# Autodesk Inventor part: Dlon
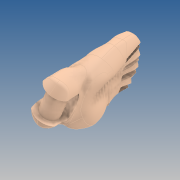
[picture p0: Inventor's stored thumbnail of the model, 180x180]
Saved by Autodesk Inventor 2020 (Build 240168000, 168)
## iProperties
Created: 2019-10
Part Number: Dlon
Material: GFRP
Document SubType Name: Modeling
Designer: yello
Density: 1.75 g/cm^3
Appearance: Default
Author: yello
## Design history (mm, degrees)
node "Palm"
workplane "Work Plane1"
workplane "Work Plane2"
sketch "Sketch13"
  geometry: L1 (0, 1.5)-(0, -1.5); A1 r 1.5 centre (0, 0) between (0, 1.5) and (0, -1.5)
  constraints: 2 end point, 2 point on circle, 1 centre point, 1 vertical
  dimensions: "d18" = 3 diameter of A1
sketch "Sketch14"
  geometry: L1 (0, -1.5)-(0, 1.5); A1 r 1.5 centre (0, 0) between (0, -1.5) and (0, 1.5); 1 further point
  constraints: 2 end point, 2 point on circle, 1 centre point, 1 vertical
  dimensions: "d19" = 3 diameter of A1
revolve "Revolution1" sketch "Sketch14" stored, may be unused: angle "d20" = 90 deg
revolve "Revolution2" stored, may be unused: angle "d21" = 90 deg
workplane "Work Plane3"
workplane "Work Plane4"
sketch "Sketch15"
  geometry: L1 (1.5, 0)-(-1.5, 0); A1 r 1.5 centre (0, 0) between (1.5, 0) and (-1.5, 0)
  constraints: 2 end point, 2 point on circle, 1 centre point
  dimensions: "d24" = 3 diameter of A1
sketch "Sketch16"
  geometry: L1 (-1.5, 0)-(1.5, 0); A1 r 1.5 centre (0, 0) between (-1.5, 0) and (1.5, 0); 1 further point
  constraints: 2 end point, 2 point on circle, 1 centre point, 1 horizontal
  dimensions: "d25" = 3 diameter of A1
revolve "Revolution3" stored, may be unused: angle "d26" = 90 deg
revolve "Revolution4" stored, may be unused: angle "d27" = 90 deg
workplane "Work Plane5"
workplane "Work Plane6"
sketch "Sketch17"
  geometry: L1 (-1.5, 0)-(1.5, 0); A1 r 1.5 centre (0, 0) between (-1.5, 0) and (1.5, 0); 1 further point
  constraints: 2 end point, 2 point on circle, 1 centre point
  dimensions: "d30" = 3 diameter of A1
sketch "Sketch18"
  geometry: L1 (0, -1.5)-(0, 1.5); A1 r 1.5 centre (0, 0) between (0, -1.5) and (0, 1.5); 1 further point
  constraints: 2 end point, 2 point on circle, 1 centre point, 1 vertical
  dimensions: "d32" = 3 diameter of A1
revolve "Revolution5" stored, may be unused: angle "d31" = 90 deg
revolve "Revolution6" stored, may be unused: angle "d33" = 90 deg
workplane "Work Plane7"
workplane "Work Plane8"
sketch "Sketch19"
  geometry: L1 (0, -1.5)-(0, 1.5); A1 r 1.5 centre (0, 0) between (0, -1.5) and (0, 1.5); 1 further point
  constraints: 2 end point, 2 point on circle, 1 centre point, 1 vertical
  dimensions: "d36" = 3 diameter of A1
sketch "Sketch20" dims "d37" = 3
  geometry: L1 (0, 1.5)-(0, -1.587); 3 further points
  constraints: 2 end point, 3 other
revolve "Revolution7" stored, may be unused: angle "d38" = 90 deg
revolve "Revolution8" stored, may be unused: angle "d39" = 90 deg
body "Solid1"
other parameters: "d16" = 0.5, "d17" = 0.5, "d22" = 0.5, "d23" = 0.5, "d28" = 0.5, "d29" = 0.5, "d34" = 0.5, "d35" = 0.5
